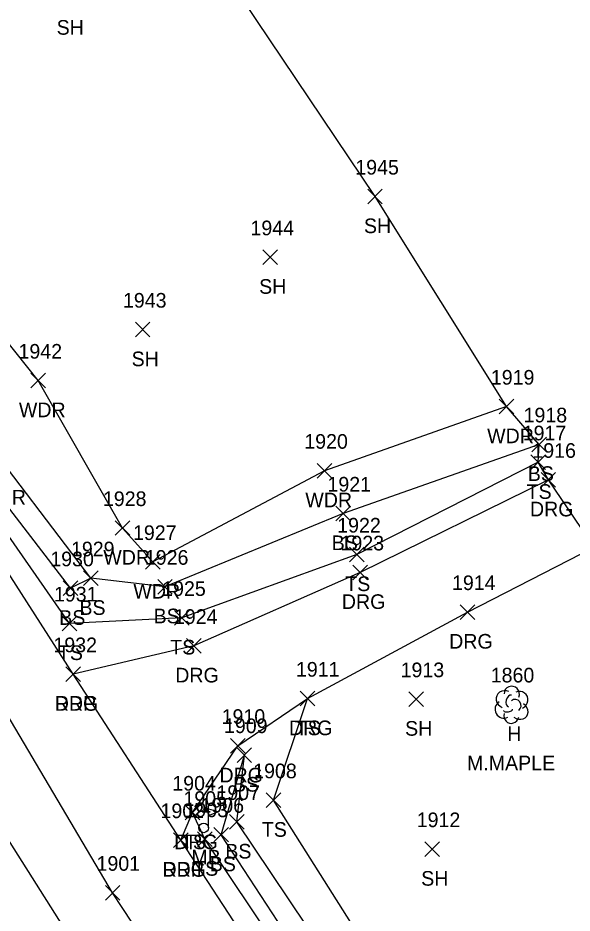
# Model space of a CAD drawing. Extents: x 1443590 to 1445966, y 578314 to 580556.
# Drawn here: x 1445049.7 to 1445125.4, y 579213.2 to 579335.5 of the extents above; entities that cross this region are included whole.
import ezdxf

# ---------------------------------------------------------------- set-up
doc = ezdxf.new("R2010")
doc.units = 0
for name, color, linetype in [('D_C', 7, 'Continuous'), ('L_A', 7, 'Continuous'), ('L_C', 7, 'Continuous'), ('L_I', 7, 'Continuous'), ('L_TIC', 7, 'Continuous'), ('LAWA', 7, 'Continuous'), ('LELB', 7, 'Continuous'), ('LMB', 7, 'Continuous'), ('LSOGP', 7, 'Continuous'), ('LTD', 7, 'Continuous'), ('P_A', 7, 'Continuous'), ('P_I', 7, 'Continuous'), ('P_TIC', 7, 'Continuous'), ('PET', 7, 'Continuous'), ('PRC', 7, 'Continuous'), ('R_A', 7, 'Continuous'), ('R_I', 7, 'Continuous'), ('R_TIC', 7, 'Continuous'), ('RDG', 7, 'Continuous')]:
    doc.layers.add(name, color=color, linetype=linetype)

msp = doc.modelspace()

# ---------------------------------------------------------------- linework, layer by layer
at = {"layer": 'L_TIC'}
for points in [[(1445097.45, 579310.06), (1445099.45, 579312.06)], [(1445099.45, 579310.06), (1445097.45, 579312.06)], [(1445083.13, 579301.77), (1445085.13, 579303.77)], [(1445085.13, 579301.77), (1445083.13, 579303.77)], [(1445065.71, 579291.88), (1445067.71, 579293.88)], [(1445067.71, 579291.88), (1445065.71, 579293.88)], [(1445051.44, 579284.91), (1445053.44, 579286.91)], [(1445053.44, 579284.91), (1445051.44, 579286.91)], [(1445115.41, 579281.36), (1445117.41, 579283.36)], [(1445117.41, 579281.36), (1445115.41, 579283.36)], [(1445119.88, 579276.2), (1445121.88, 579278.2)], [(1445121.88, 579276.2), (1445119.88, 579278.2)], [(1445119.75, 579273.75), (1445121.75, 579275.75)], [(1445121.75, 579273.75), (1445119.75, 579275.75)], [(1445090.57, 579272.6), (1445092.57, 579274.6)], [(1445092.57, 579272.6), (1445090.57, 579274.6)], [(1445093.09, 579266.75), (1445095.09, 579268.75)], [(1445095.09, 579266.75), (1445093.09, 579268.75)], [(1445062.97, 579264.77), (1445064.97, 579266.77)], [(1445064.97, 579264.77), (1445062.97, 579266.77)], [(1445094.98, 579261.15), (1445096.98, 579263.15)], [(1445096.98, 579261.15), (1445094.98, 579263.15)], [(1445067.08, 579260.13), (1445069.08, 579262.13)], [(1445069.08, 579260.13), (1445067.08, 579262.13)], [(1445058.62, 579257.9), (1445060.62, 579259.9)], [(1445060.62, 579257.9), (1445058.62, 579259.9)], [(1445058.62, 579257.9), (1445060.62, 579259.9)], [(1445060.62, 579257.9), (1445058.62, 579259.9)], [(1445068.76, 579256.75), (1445070.76, 579258.75)], [(1445070.76, 579256.75), (1445068.76, 579258.75)], [(1445055.87, 579256.54), (1445057.87, 579258.54)], [(1445057.87, 579256.54), (1445055.87, 579258.54)], [(1445071.07, 579252.49), (1445073.07, 579254.49)], [(1445073.07, 579252.49), (1445071.07, 579254.49)], [(1445055.72, 579251.73), (1445057.72, 579253.73)], [(1445057.72, 579251.73), (1445055.72, 579253.73)], [(1445088.21, 579241.46), (1445090.21, 579243.46)], [(1445090.21, 579241.46), (1445088.21, 579243.46)], [(1445103.08, 579241.39), (1445105.08, 579243.39)], [(1445105.08, 579241.39), (1445103.08, 579243.39)], [(1445079.6, 579233.75), (1445081.6, 579235.75)], [(1445081.6, 579233.75), (1445079.6, 579235.75)], [(1445079.6, 579233.75), (1445081.6, 579235.75)], [(1445081.6, 579233.75), (1445079.6, 579235.75)], [(1445083.59, 579227.58), (1445085.59, 579229.58)], [(1445085.59, 579227.58), (1445083.59, 579229.58)], [(1445072.53, 579225.89), (1445074.53, 579227.89)], [(1445074.53, 579225.89), (1445072.53, 579227.89)], [(1445078.56, 579224.61), (1445080.56, 579226.61)], [(1445080.56, 579224.61), (1445078.56, 579226.61)], [(1445076.44, 579222.87), (1445078.44, 579224.87)], [(1445078.44, 579222.87), (1445076.44, 579224.87)], [(1445074.2, 579222.26), (1445076.2, 579224.26)], [(1445076.2, 579222.26), (1445074.2, 579224.26)], [(1445105.28, 579220.9), (1445107.28, 579222.9)], [(1445107.28, 579220.9), (1445105.28, 579222.9)]]:
    msp.add_lwpolyline(points, dxfattribs=at)
at = {"layer": 'LAWA'}
msp.add_lwpolyline([(1445116.41, 579282.36), (1445091.57, 579273.6), (1445068.08, 579261.13), (1445063.97, 579265.77), (1445052.44, 579285.91), (1445030.61, 579313.29), (1445007.29, 579349.44), (1444981.88, 579393.33), (1444958.1, 579429.17), (1444930.43, 579469.34), (1444907.58, 579503.94), (1444877.79, 579540.6), (1444853.64, 579577.69), (1444828.42, 579618.05), (1444811.24, 579649.86), (1444793.14, 579680.39), (1444780.3, 579709.09)], dxfattribs=at)
at = {"layer": 'LELB'}
for points in [[(1445059.62, 579258.9), (1445043.89, 579279.61), (1445024.59, 579310.38), (1445003.03, 579346.49), (1444976.79, 579389.55), (1444952.41, 579425.12), (1444926.34, 579464.68), (1444902.15, 579500.76), (1444874.51, 579538.34), (1444849.34, 579574.14), (1444822.42, 579614.33), (1444804.62, 579646.57), (1444787.75, 579677.64), (1444772.75, 579706.54)], [(1445120.88, 579277.2), (1445094.09, 579267.75), (1445069.76, 579257.75), (1445059.62, 579258.9), (1445056.87, 579257.54), (1445041.61, 579277.38), (1445040.78, 579278.47), (1445023.19, 579309.75), (1445001.25, 579344.99), (1444974.42, 579387.92), (1444950.97, 579424.44), (1444924.55, 579463.55), (1444901.05, 579499.1), (1444872.7, 579536.92), (1444847.2, 579572.49), (1444820.99, 579613.47), (1444802.94, 579645.55), (1444786.24, 579676.71), (1444770.75, 579705.77)], [(1445120.75, 579274.75), (1445095.98, 579262.15), (1445072.07, 579253.49), (1445056.72, 579252.73), (1445039.69, 579277.16), (1445039.13, 579277.92), (1445021.32, 579309.06), (1444999.24, 579343.98), (1444972.54, 579386.39), (1444948.75, 579423.47), (1444922.09, 579461.69), (1444897.81, 579497.23), (1444870.77, 579536.13), (1444845.96, 579571.78), (1444819.96, 579613.15), (1444802.08, 579645.41), (1444784.76, 579676.08), (1444769.89, 579705.02)], [(1445175.89, 579120.33), (1445161.09, 579128.73), (1445144.66, 579138.54), (1445128.14, 579162.61), (1445109.64, 579188.96), (1445084.59, 579228.58), (1445089.21, 579242.46)], [(1445260.44, 579122.72), (1445223.01, 579115.29), (1445192.84, 579112.59), (1445181.19, 579112.4), (1445175.9, 579109.85), (1445157.36, 579117.17), (1445139.46, 579131.71), (1445137.95, 579131.54), (1445137.45, 579132.58), (1445137.4, 579133.97), (1445121.19, 579158.43), (1445103, 579184.76), (1445077.44, 579223.87), (1445080.6, 579234.75)], [(1445181.19, 579112.4), (1445159.29, 579120.5), (1445139.76, 579133.3), (1445138.49, 579135.03), (1445122.96, 579159.67), (1445105.77, 579186.61), (1445079.56, 579225.61), (1445080.6, 579234.75)], [(1445175.9, 579109.85), (1445156.75, 579115.92), (1445137.26, 579129.47), (1445135.12, 579132.39), (1445119.39, 579157.71), (1445101.62, 579183.82), (1445075.2, 579223.26), (1445073.53, 579226.89)]]:
    msp.add_lwpolyline(points, dxfattribs=at)
at = {"layer": 'LMB'}
for p, q in [((1445075.7, 579227.4), (1445077, 579227.02)), ((1445075.71, 579224.81), (1445075.71, 579227.41)), ((1445075.71, 579226.5), (1445076.99, 579227.01)), ((1445075.05, 579224.8), (1445075.05, 579224.8))]:
    msp.add_line(p, q, dxfattribs=at)
msp.add_circle((1445075.05, 579224.8), 0.656, dxfattribs=at)
at = {"layer": 'LSOGP'}
msp.add_lwpolyline([(1445128.37, 579263.15), (1445122.13, 579272.36), (1445120.75, 579274.75), (1445120.88, 579277.2), (1445116.41, 579282.35), (1445098.46, 579311.06), (1445076.81, 579343.35)], dxfattribs=at)
at = {"layer": 'LTD'}
msp.add_line((1445117.08, 579241.67), (1445117.08, 579241.67), dxfattribs=at)
msp.add_line((1445117.08, 579241.67), (1445117.08, 579241.67), dxfattribs=at)
msp.add_arc((1445117.13, 579243.11), 1.05, 335.5272, 180.9563, dxfattribs=at)
for centre, major_axis, ratio, start_param, end_param in [((1445116.29, 579242.34), (1.21, -0.51), 0.895232, 1.570796, 4.712389), ((1445116.88, 579242.13), (-0.208, -0.792), 0.645439, 3.141593, 6.283185), ((1445118.13, 579242.26), (-1.14, -0.48), 0.949671, 1.570796, 4.712389), ((1445116, 579240.97), (0.58, -1.04), 0.959034, 3.141593, 6.283185), ((1445117.58, 579241.51), (-0.5, 0.667), 0.989748, 3.141593, 6.283185), ((1445118.08, 579240.84), (-1.09, 0.79), 0.841452, 1.570796, 4.712389), ((1445117.08, 579240.17), (0.26, 1.06), 0.942809, 1.570796, 4.712389), ((1445116.63, 579240.92), (-0.625, -0.083), 0.423636, 0, 3.141593)]:
    msp.add_ellipse(centre, major_axis=major_axis, ratio=ratio, start_param=start_param, end_param=end_param, dxfattribs=at)
at = {"layer": 'P_TIC'}
for points in [[(1445056.22, 579244.8), (1445058.22, 579246.8)], [(1445058.22, 579244.8), (1445056.22, 579246.8)], [(1445070.93, 579222.13), (1445072.93, 579224.13)], [(1445072.93, 579222.13), (1445070.93, 579224.13)], [(1445061.61, 579214.94), (1445063.61, 579216.94)], [(1445063.61, 579214.94), (1445061.61, 579216.94)]]:
    msp.add_lwpolyline(points, dxfattribs=at)
at = {"layer": 'PET'}
for points in [[(1445187.64, 579104.95), (1445149.35, 579115.57), (1445134.36, 579130.22), (1445115.96, 579155.83), (1445098.76, 579182.02), (1445071.93, 579223.13), (1445057.22, 579245.8), (1445037.84, 579275.94), (1445019.3, 579308.07), (1444997.05, 579342.56), (1444969.98, 579385.25), (1444946.15, 579421.86), (1444919.7, 579460.87), (1444895.29, 579496.39), (1444868.39, 579534.19), (1444844.21, 579570.94), (1444818.42, 579612.05), (1444800.46, 579644.42), (1444783.19, 579675.42), (1444768.08, 579703.75)], [(1444749.57, 579692.99), (1444767.18, 579659.68), (1444778.42, 579640.07), (1444792.21, 579615.83), (1444803.11, 579597.28), (1444822.86, 579565.6), (1444843.8, 579533.42), (1444869.08, 579496.25), (1444890.19, 579465.65), (1444913.09, 579433.16), (1444937.14, 579397.54), (1444963.6, 579356.94), (1444983.04, 579326.35), (1445006.82, 579289.13), (1445021.79, 579264.22), (1445044.58, 579229.01), (1445059.66, 579205.24), (1445081.95, 579172.07), (1445091.01, 579154.93), (1445104.63, 579132.07), (1445107.77, 579117.84), (1445102.26, 579109.52), (1445094.76, 579101.93)]]:
    msp.add_lwpolyline(points, dxfattribs=at)
at = {"layer": 'PRC'}
msp.add_lwpolyline([(1445134.69, 579101.81), (1445120.96, 579124.75), (1445105.7, 579149.31), (1445088.61, 579176.47), (1445062.61, 579215.94), (1445046.37, 579243.3), (1445028.61, 579272.2), (1445009.91, 579303.07), (1444988.59, 579337.21), (1444961.47, 579379.67), (1444937.03, 579417.04), (1444911.02, 579455.05), (1444885.8, 579491.61), (1444860.37, 579528.28), (1444835.41, 579566.04), (1444809.93, 579606.59), (1444790.8, 579639.57), (1444773.48, 579670.26), (1444758.9, 579698.36)], dxfattribs=at)
at = {"layer": 'R_TIC'}
for points in [[(1445121.13, 579271.36), (1445123.13, 579273.36)], [(1445123.13, 579271.36), (1445121.13, 579273.36)], [(1445095.43, 579258.71), (1445097.43, 579260.71)], [(1445097.43, 579258.71), (1445095.43, 579260.71)], [(1445110.09, 579253.29), (1445112.09, 579255.29)], [(1445112.09, 579253.29), (1445110.09, 579255.29)], [(1445072.68, 579248.67), (1445074.68, 579250.67)], [(1445074.68, 579248.67), (1445072.68, 579250.67)], [(1445056.22, 579244.8), (1445058.22, 579246.8)], [(1445058.22, 579244.8), (1445056.22, 579246.8)], [(1445088.21, 579241.46), (1445090.21, 579243.46)], [(1445090.21, 579241.46), (1445088.21, 579243.46)], [(1445078.71, 579235.01), (1445080.71, 579237.01)], [(1445080.71, 579235.01), (1445078.71, 579237.01)], [(1445072.53, 579225.89), (1445074.53, 579227.89)], [(1445074.53, 579225.89), (1445072.53, 579227.89)], [(1445070.93, 579222.13), (1445072.93, 579224.13)], [(1445072.93, 579222.13), (1445070.93, 579224.13)]]:
    msp.add_lwpolyline(points, dxfattribs=at)
at = {"layer": 'RDG'}
for points in [[(1445122.13, 579272.36), (1445096.43, 579259.71), (1445073.68, 579249.67), (1445057.22, 579245.8)], [(1445071.93, 579223.13), (1445073.53, 579226.89), (1445079.71, 579236.01), (1445089.21, 579242.46), (1445111.09, 579254.29), (1445128.37, 579263.15)]]:
    msp.add_lwpolyline(points, dxfattribs=at)

# ---------------------------------------------------------------- texts
at = {"layer": 'D_C'}
msp.add_text('18" CGMP FAIR', height=2, dxfattribs=at).set_placement((1445031.23, 579268.98))
at = {"layer": 'L_A'}
for s, p in [('SH', (1445054.96, 579333.17)), ('SH', (1445096.94, 579306.06)), ('SH', (1445082.62, 579297.77)), ('SH', (1445065.2, 579287.88)), ('WDR', (1445049.8, 579280.91)), ('WDR', (1445113.77, 579277.36)), ('BS', (1445119.32, 579272.2)), ('TS', (1445119.16, 579269.75)), ('WDR', (1445088.93, 579268.6)), ('BS', (1445092.53, 579262.75)), ('WDR', (1445061.33, 579260.77)), ('TS', (1445094.39, 579257.15)), ('WDR', (1445065.44, 579256.13)), ('BS', (1445058.07, 579253.9)), ('BS', (1445058.07, 579253.9)), ('BS', (1445055.31, 579252.54)), ('BS', (1445068.2, 579252.75)), ('TS', (1445070.48, 579248.49)), ('TS', (1445055.13, 579247.73)), ('TS', (1445087.62, 579237.46)), ('SH', (1445102.56, 579237.39)), ('H', (1445116.52, 579236.67)), ('BS', (1445079.04, 579229.75)), ('BS', (1445079.04, 579229.75)), ('TS', (1445082.99, 579223.58)), ('TS', (1445071.94, 579221.89)), ('BS', (1445078, 579220.61)), ('MB', (1445073.36, 579219.8)), ('BS', (1445075.88, 579218.87)), ('TS', (1445073.61, 579218.26)), ('SH', (1445104.76, 579216.9))]:
    msp.add_text(s, height=2, dxfattribs=at).set_placement(p)
at = {"layer": 'L_C'}
msp.add_text('M.MAPLE', height=2, dxfattribs=at).set_placement((1445111.02, 579232.67))
at = {"layer": 'L_I'}
for s, p in [('1945', (1445095.76, 579314.06)), ('1944', (1445081.44, 579305.77)), ('1943', (1445064.02, 579295.88)), ('1942', (1445049.75, 579288.91)), ('1919', (1445114.28, 579285.36)), ('1918', (1445118.75, 579280.2)), ('1917', (1445118.63, 579277.75)), ('1920', (1445088.79, 579276.6)), ('1921', (1445091.96, 579270.75)), ('1928', (1445061.28, 579268.77)), ('1927', (1445065.39, 579264.13)), ('1922', (1445093.29, 579265.15)), ('1929', (1445056.92, 579261.9)), ('1929', (1445056.92, 579261.9)), ('1930', (1445054.09, 579260.54)), ('1926', (1445067.01, 579260.75)), ('1931', (1445054.59, 579255.73)), ('1925', (1445069.38, 579256.49)), ('1911', (1445087.65, 579245.46)), ('1913', (1445101.95, 579245.39)), ('1860', (1445114.26, 579244.67)), ('1909', (1445077.82, 579237.75)), ('1909', (1445077.82, 579237.75)), ('1908', (1445081.81, 579231.58)), ('1904', (1445070.76, 579229.89)), ('1907', (1445076.79, 579228.61)), ('1905', (1445072.28, 579227.8)), ('1903', (1445072.43, 579226.26)), ('1906', (1445074.61, 579226.87)), ('1912', (1445104.15, 579224.9))]:
    msp.add_text(s, height=2, dxfattribs=at).set_placement(p)
at = {"layer": 'P_A'}
for p in [(1445054.7, 579240.8), (1445069.41, 579218.13)]:
    msp.add_text('RDP', height=2, dxfattribs=at).set_placement(p)
at = {"layer": 'P_I'}
for s, p in [('1932', (1445054.52, 579248.8)), ('1902', (1445069.15, 579226.13)), ('1901', (1445060.41, 579218.94))]:
    msp.add_text(s, height=2, dxfattribs=at).set_placement(p)
at = {"layer": 'R_A'}
for p in [(1445119.62, 579267.36), (1445093.92, 579254.71), (1445108.58, 579249.29), (1445071.16, 579244.67), (1445054.7, 579240.8), (1445086.7, 579237.46), (1445077.2, 579231.01), (1445071.02, 579221.89), (1445069.41, 579218.13)]:
    msp.add_text('DRG', height=2, dxfattribs=at).set_placement(p)
at = {"layer": 'R_I'}
for s, p in [('1916', (1445119.95, 579275.36)), ('1923', (1445093.74, 579262.71)), ('1914', (1445108.97, 579257.29)), ('1924', (1445070.98, 579252.67)), ('1932', (1445054.52, 579248.8)), ('1911', (1445087.65, 579245.46)), ('1910', (1445077.5, 579239.01)), ('1904', (1445070.76, 579229.89)), ('1902', (1445069.15, 579226.13))]:
    msp.add_text(s, height=2, dxfattribs=at).set_placement(p)

doc.saveas('drawing.dxf')
